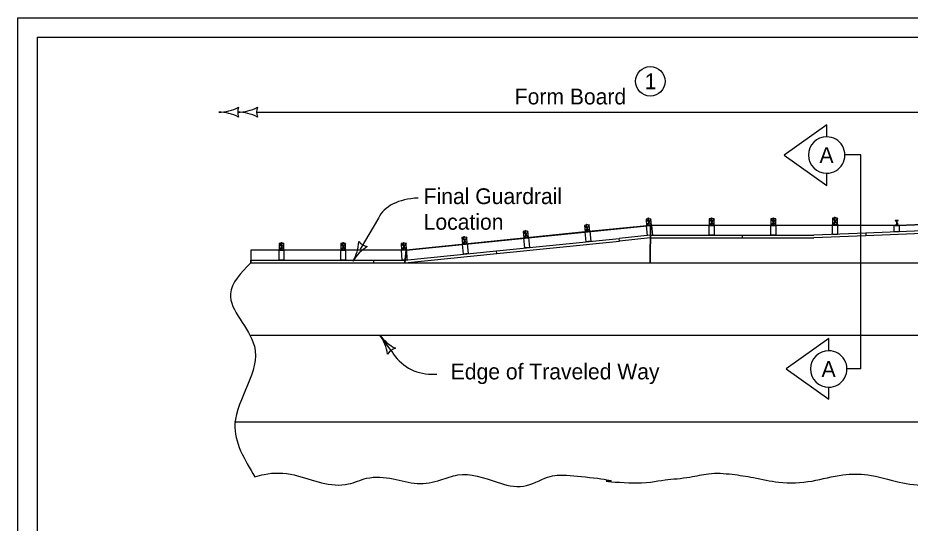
# Model space of a CAD drawing. Extents: x 10133 to 81668, y 7924 to 12229.
# Drawn here: x 10133 to 11037, y 9431 to 9944 of the extents above; entities that cross this region are included whole.
import ezdxf

# ---------------------------------------------------------------- set-up
doc = ezdxf.new("R2010")
doc.units = 0
for name, color, linetype in [('Cell', 7, 'Continuous'), ('dsnTextFinalPlan', 7, 'Continuous'), ('Level 1', 7, 'Continuous'), ('Level 12', 7, 'Continuous'), ('Level 4', 7, 'Continuous'), ('Level 5', 7, 'Continuous'), ('Level 6', 7, 'Continuous'), ('Level 7', 7, 'Continuous'), ('SheetBorder', 7, 'Continuous')]:
    doc.layers.add(name, color=color, linetype=linetype)

msp = doc.modelspace()

# ---------------------------------------------------------------- linework, layer by layer
at = {"layer": 'Cell'}
for p, q in [((11025.35, 9738.32), (11022.02, 9738.32)), ((11022.02, 9738.32), (11022.02, 9738.16)), ((11022.02, 9738.32), (11022.02, 9738.16)), ((11025.35, 9738.32), (11022.02, 9738.32)), ((11022.02, 9738.16), (11023.19, 9738.16)), ((11022.02, 9738.16), (11023.19, 9738.16)), ((11023.61, 9737.75), (11023.61, 9734)), ((11023.61, 9737.75), (11023.61, 9734)), ((11023.77, 9734), (11023.77, 9737.75)), ((11023.77, 9734), (11023.77, 9737.75)), ((11024.18, 9738.16), (11025.35, 9738.16)), ((11024.18, 9738.16), (11025.35, 9738.16)), ((11025.35, 9738.16), (11025.35, 9738.32)), ((11025.35, 9738.16), (11025.35, 9738.32)), ((11021.08, 9726.77), (11021.08, 9733.74)), ((11021.08, 9733.74), (11021.71, 9733.74)), ((11021.71, 9733.42), (11021.71, 9733.74)), ((11025.46, 9733.42), (11021.71, 9733.42)), ((11023.19, 9733.58), (11022.02, 9733.58)), ((11022.02, 9733.58), (11022.02, 9733.42)), ((11022.02, 9733.58), (11022.02, 9733.42)), ((11023.19, 9733.58), (11022.02, 9733.58)), ((11022.02, 9733.42), (11025.35, 9733.42)), ((11022.02, 9733.42), (11025.35, 9733.42)), ((11024, 9734.1), (11023.92, 9734.05)), ((11024, 9734.1), (11023.92, 9734.05)), ((11023.92, 9734.05), (11023.92, 9733.67)), ((11023.92, 9733.67), (11023.92, 9734.05)), ((11024, 9734.1), (11024.97, 9734.1)), ((11024.97, 9734.1), (11024, 9734.1)), ((11025.35, 9733.58), (11024.18, 9733.58)), ((11025.35, 9733.58), (11024.18, 9733.58)), ((11024.22, 9734.05), (11024.22, 9733.63)), ((11024.22, 9733.63), (11024.22, 9734.05)), ((11024.22, 9733.63), (11024.22, 9734.05)), ((11024.78, 9735.61), (11024.26, 9735.61)), ((11024.26, 9735.61), (11024.26, 9734.1)), ((11024.78, 9735.61), (11024.26, 9735.61)), ((11024.26, 9735.61), (11024.26, 9734.1)), ((11024.26, 9734.1), (11024.78, 9734.1)), ((11024.78, 9734.1), (11024.78, 9735.61)), ((11024.78, 9734.1), (11024.78, 9735.61)), ((11024.82, 9733.63), (11024.82, 9734.05)), ((11024.82, 9734.05), (11024.82, 9733.63)), ((11024.82, 9733.63), (11024.82, 9734.05)), ((11024.97, 9734.1), (11025.04, 9734.1)), ((11025.04, 9734.1), (11024.97, 9734.1)), ((11025.12, 9734.05), (11025.04, 9734.1)), ((11025.12, 9734.05), (11025.04, 9734.1)), ((11025.04, 9733.58), (11025.12, 9733.63)), ((11025.04, 9733.58), (11025.12, 9733.63)), ((11025.12, 9733.63), (11025.12, 9734.05)), ((11025.12, 9733.63), (11025.12, 9734.05)), ((11025.35, 9733.42), (11025.35, 9733.58)), ((11025.35, 9733.42), (11025.35, 9733.58)), ((11025.46, 9733.74), (11026.08, 9733.74)), ((11025.46, 9733.74), (11025.46, 9733.42)), ((11026.08, 9733.74), (11026.08, 9726.77)), ((11026.08, 9726.77), (11021.08, 9726.77))]:
    msp.add_line(p, q, dxfattribs=at)
for points in [[(11023.92, 9733.67), (11023.92, 9733.67)], [(11024.18, 9733.58), (11025.04, 9733.58), (11025.04, 9733.58)]]:
    msp.add_lwpolyline(points, dxfattribs=at)
for centre, start, end in [((11023.19, 9737.75), 359.99336, 90.00253), ((11023.19, 9737.75), 359.99336, 90.00253), ((11024.18, 9737.75), 90.00734, 179.99635), ((11024.18, 9737.75), 90.00734, 179.99635), ((11023.19, 9734), 270.00734, 359.99635), ((11023.19, 9734), 270.00734, 359.99635), ((11024.18, 9734), 179.99336, 270.00253), ((11024.18, 9734), 179.99336, 270.00253), ((11024.18, 9734), 230.88662, 270.00253)]:
    msp.add_arc(centre, 0.417, start, end, dxfattribs=at)
for points in [[(11024.22, 9734.05), (11024.2, 9734.06), (11024.15, 9734.09), (11024.06, 9734.1), (11023.99, 9734.09), (11023.94, 9734.06), (11023.92, 9734.05)], [(11024.22, 9734.05), (11024.2, 9734.06), (11024.15, 9734.09), (11024.06, 9734.1), (11023.99, 9734.09), (11023.94, 9734.06), (11023.92, 9734.05)], [(11023.92, 9734.05), (11023.94, 9734.06), (11023.99, 9734.09), (11024.06, 9734.1), (11024.15, 9734.09), (11024.2, 9734.06), (11024.22, 9734.05)], [(11024.12, 9733.59), (11024.13, 9733.59), (11024.17, 9733.6), (11024.2, 9733.62), (11024.22, 9733.63)], [(11024.82, 9734.05), (11024.77, 9734.06), (11024.66, 9734.09), (11024.51, 9734.1), (11024.36, 9734.09), (11024.27, 9734.06), (11024.22, 9734.05)], [(11024.82, 9734.05), (11024.77, 9734.06), (11024.66, 9734.09), (11024.51, 9734.1), (11024.36, 9734.09), (11024.27, 9734.06), (11024.22, 9734.05)], [(11024.22, 9734.05), (11024.27, 9734.06), (11024.36, 9734.09), (11024.51, 9734.1), (11024.66, 9734.09), (11024.77, 9734.06), (11024.82, 9734.05)], [(11024.22, 9733.63), (11024.27, 9733.62), (11024.38, 9733.59), (11024.54, 9733.58), (11024.69, 9733.59), (11024.78, 9733.62), (11024.82, 9733.63)], [(11024.82, 9733.63), (11024.78, 9733.62), (11024.69, 9733.59), (11024.54, 9733.58), (11024.38, 9733.59), (11024.27, 9733.62), (11024.22, 9733.63)], [(11024.22, 9733.63), (11024.27, 9733.62), (11024.38, 9733.59), (11024.54, 9733.58), (11024.69, 9733.59), (11024.78, 9733.62), (11024.82, 9733.63)], [(11025.12, 9734.05), (11025.11, 9734.06), (11025.07, 9734.08), (11025.01, 9734.1), (11024.94, 9734.1), (11024.87, 9734.08), (11024.83, 9734.06), (11024.82, 9734.05)], [(11025.12, 9734.05), (11025.11, 9734.06), (11025.07, 9734.08), (11025.01, 9734.1), (11024.94, 9734.1), (11024.87, 9734.08), (11024.83, 9734.06), (11024.82, 9734.05)], [(11024.82, 9734.05), (11024.83, 9734.06), (11024.87, 9734.08), (11024.94, 9734.1), (11025.01, 9734.1), (11025.07, 9734.08), (11025.11, 9734.06), (11025.12, 9734.05)], [(11024.82, 9733.63), (11024.83, 9733.63), (11024.87, 9733.6), (11024.94, 9733.58), (11025.01, 9733.58), (11025.07, 9733.6), (11025.11, 9733.62), (11025.12, 9733.63)], [(11025.12, 9733.63), (11025.11, 9733.62), (11025.07, 9733.6), (11025.01, 9733.58), (11024.94, 9733.58), (11024.87, 9733.6), (11024.83, 9733.63), (11024.82, 9733.63)], [(11024.82, 9733.63), (11024.83, 9733.63), (11024.87, 9733.6), (11024.94, 9733.58), (11025.01, 9733.58), (11025.07, 9733.6), (11025.11, 9733.62), (11025.12, 9733.63)]]:
    msp.add_open_spline(points, degree=3, dxfattribs=at)
at = {"layer": 'dsnTextFinalPlan'}
for p, q in [((11025.35, 9733.42), (11500.75, 9752.95)), ((11403.96, 9741.99), (10992.39, 9725.53)), ((11404.06, 9739.28), (10992.39, 9722.82)), ((11022.02, 9738.32), (11022.02, 9738.16)), ((11025.35, 9738.32), (11022.02, 9738.32)), ((11022.02, 9738.16), (11023.19, 9738.16)), ((11023.61, 9737.75), (11023.61, 9734)), ((11023.77, 9734), (11023.77, 9737.75)), ((11024.18, 9738.16), (11025.35, 9738.16)), ((11025.35, 9738.16), (11025.35, 9738.32)), ((10526.39, 9708.35), (10774.18, 9733.42)), ((11022.02, 9733.42), (10774.18, 9733.42)), ((11021.08, 9726.77), (11021.08, 9733.74)), ((11021.08, 9733.74), (11021.71, 9733.74)), ((11021.71, 9733.42), (11021.71, 9733.74)), ((11025.46, 9733.42), (11021.71, 9733.42)), ((11022.02, 9733.58), (11022.02, 9733.42)), ((11023.19, 9733.58), (11022.02, 9733.58)), ((11022.02, 9733.42), (11025.35, 9733.42)), ((11024, 9734.1), (11023.92, 9734.05)), ((11023.92, 9733.67), (11023.92, 9734.05)), ((11024, 9734.1), (11024.97, 9734.1)), ((11025.35, 9733.58), (11024.18, 9733.58)), ((11024.22, 9733.63), (11024.22, 9734.05)), ((11024.78, 9735.61), (11024.26, 9735.61)), ((11024.26, 9735.61), (11024.26, 9734.1)), ((11024.78, 9734.1), (11024.78, 9735.61)), ((11024.82, 9733.63), (11024.82, 9734.05)), ((11024.97, 9734.1), (11025.04, 9734.1)), ((11025.12, 9734.05), (11025.04, 9734.1)), ((11025.04, 9733.58), (11025.12, 9733.63)), ((11025.12, 9733.63), (11025.12, 9734.05)), ((11025.35, 9733.42), (11025.35, 9733.58)), ((11025.46, 9733.74), (11026.08, 9733.74)), ((11025.46, 9733.74), (11025.46, 9733.42)), ((11026.08, 9733.74), (11026.08, 9726.77)), ((10992.39, 9725.53), (10939.63, 9723.42)), ((10992.5, 9722.82), (10939.65, 9720.71)), ((10992.39, 9725.53), (10992.5, 9722.82)), ((10992.39, 9725.53), (10992.5, 9722.82)), ((11026.08, 9726.77), (11021.08, 9726.77)), ((10368.67, 9708.35), (10368.64, 9698.34)), ((10526.39, 9708.35), (10368.67, 9708.35)), ((10368.64, 9695.63), (11982.35, 9695.63)), ((10368.86, 9622), (11982.65, 9622))]:
    msp.add_line(p, q, dxfattribs=at)
for centre, start, end in [((11023.19, 9737.75), 359.99336, 90.00253), ((11024.18, 9737.75), 90.00734, 179.99635), ((11023.19, 9734), 270.00734, 359.99635), ((11024.18, 9734), 264.71743, 270.00253)]:
    msp.add_arc(centre, 0.417, start, end, dxfattribs=at)
for points in [[(11024.22, 9734.05), (11024.2, 9734.06), (11024.15, 9734.09), (11024.06, 9734.1), (11023.99, 9734.09), (11023.94, 9734.06), (11023.92, 9734.05)], [(11024.12, 9733.59), (11024.13, 9733.59), (11024.17, 9733.6), (11024.2, 9733.62), (11024.22, 9733.63)], [(11024.82, 9734.05), (11024.77, 9734.06), (11024.66, 9734.09), (11024.51, 9734.1), (11024.36, 9734.09), (11024.27, 9734.06), (11024.22, 9734.05)], [(11024.22, 9733.63), (11024.27, 9733.62), (11024.38, 9733.59), (11024.54, 9733.58), (11024.69, 9733.59), (11024.78, 9733.62), (11024.82, 9733.63)], [(11025.12, 9734.05), (11025.11, 9734.06), (11025.07, 9734.08), (11025.01, 9734.1), (11024.94, 9734.1), (11024.87, 9734.08), (11024.83, 9734.06), (11024.82, 9734.05)], [(11024.82, 9733.63), (11024.83, 9733.63), (11024.87, 9733.6), (11024.94, 9733.58), (11025.01, 9733.58), (11025.07, 9733.6), (11025.11, 9733.62), (11025.12, 9733.63)]]:
    msp.add_open_spline(points, degree=3, dxfattribs=at)
for points in [[(10368.64, 9695.63), (10347.99, 9664.08), (10372.36, 9611), (10352.66, 9531.9), (10372.93, 9478.29)], [(10372.93, 9478.29), (10382.36, 9480.86), (10412.58, 9480.29), (10440.52, 9472.31), (10467.89, 9471.16), (10486.14, 9476.87), (10512.94, 9476.3), (10537.46, 9471.74), (10561.41, 9475.16), (10578.52, 9480.29), (10618.43, 9472.88), (10645.23, 9468.88), (10669.75, 9478.01), (10692.56, 9479.72), (10731.34, 9474.02), (10730.77, 9474.02), (10751.92, 9472.41), (10788.99, 9475.27), (10814.08, 9478.12), (10832.9, 9481.54), (10856.85, 9480.97), (10878.51, 9477.55), (10904.17, 9472.98), (10937.82, 9474.13), (10969.18, 9480.4), (10994.27, 9480.4), (11026.2, 9472.98), (11055.29, 9470.13), (11088.93, 9476.98), (11121.43, 9480.4), (11155.65, 9473.55), (11181.31, 9470.7), (11203.54, 9474.13), (11231.49, 9489.53), (11241.75, 9491.81), (11266.27, 9494.09), (11296.93, 9494.66), (11318.03, 9494.66), (11371.34, 9485.38)]]:
    msp.add_spline(points, degree=3, dxfattribs=at)
at = {"layer": 'Level 1'}
for q in [(10152.18, 8314.36), (13247.87, 9924.36)]:
    msp.add_line((10152.18, 9924.36), q, dxfattribs=at)
at = {"layer": 'Level 12'}
msp.add_circle((10773.85, 9879.62), 15, dxfattribs=at)
at = {"layer": 'Level 4'}
for p, q in [((10769.49, 9739.76), (10775.13, 9733.62)), ((10774.47, 9740.26), (10770.15, 9733.13)), ((10771.88, 9740.98), (10771.87, 9741.04)), ((10772.64, 9733.37), (10771.98, 9740.01)), ((10833.64, 9740.09), (10838.64, 9733.42)), ((10838.64, 9740.09), (10833.64, 9733.42)), ((10836.14, 9741.06), (10836.14, 9741.13)), ((10836.14, 9733.42), (10836.14, 9740.09)), ((10896.14, 9740.09), (10901.14, 9733.42)), ((10901.14, 9740.09), (10896.14, 9733.42)), ((10898.64, 9741.06), (10898.64, 9741.13)), ((10898.64, 9733.42), (10898.64, 9740.09)), ((10958.64, 9740.95), (10963.64, 9734.28)), ((10963.64, 9740.95), (10958.64, 9734.28)), ((10961.14, 9741.92), (10961.14, 9741.99)), ((10961.14, 9734.28), (10961.14, 9740.95)), ((10644.84, 9727.23), (10650.48, 9721.1)), ((10649.81, 9727.73), (10645.51, 9720.6)), ((10647.23, 9728.45), (10647.22, 9728.52)), ((10647.99, 9720.85), (10647.33, 9727.48)), ((10707.03, 9733.48), (10712.67, 9727.35)), ((10712, 9733.98), (10707.69, 9726.85)), ((10707.69, 9726.85), (10712.67, 9727.35)), ((10709.42, 9734.7), (10709.41, 9734.77)), ((10710.18, 9727.1), (10709.51, 9733.73)), ((10712.67, 9727.35), (10713.67, 9717.39)), ((10770.15, 9733.13), (10775.13, 9733.62)), ((10772.64, 9733.37), (10770.15, 9733.13)), ((10772.64, 9733.37), (10770.15, 9733.13)), ((10771.15, 9723.17), (10770.15, 9733.13)), ((10775.13, 9733.62), (10776.13, 9723.66)), ((10833.64, 9733.42), (10838.64, 9733.42)), ((10833.64, 9723.42), (10833.64, 9733.42)), ((10838.64, 9733.42), (10838.64, 9723.42)), ((10896.14, 9733.42), (10901.14, 9733.42)), ((10896.14, 9723.42), (10896.14, 9733.42)), ((10901.14, 9733.42), (10901.14, 9723.42)), ((10958.64, 9734.28), (10963.64, 9734.28)), ((10958.64, 9724.28), (10958.64, 9734.28)), ((10963.64, 9734.28), (10963.64, 9724.28)), ((10582.66, 9721.02), (10588.3, 9714.85)), ((10587.64, 9721.52), (10583.33, 9714.35)), ((10585.05, 9722.24), (10585.05, 9722.31)), ((10585.81, 9714.6), (10585.15, 9721.27)), ((10617.9, 9707.76), (10742.28, 9720.26)), ((10645.51, 9720.6), (10650.49, 9721.1)), ((10646.51, 9710.64), (10645.51, 9720.6)), ((10650.49, 9721.1), (10651.49, 9711.14)), ((10708.69, 9716.89), (10707.69, 9726.85)), ((10773.64, 9723.42), (10742.28, 9720.26)), ((10742.55, 9717.57), (10742.28, 9720.26)), ((10742.55, 9717.58), (10742.28, 9720.26)), ((10773.64, 9720.71), (10742.55, 9717.58)), ((10776.13, 9723.66), (10771.15, 9723.17)), ((10773.64, 9723.42), (10867.39, 9723.42)), ((10773.64, 9720.71), (10867.39, 9720.71)), ((10838.64, 9723.42), (10833.64, 9723.42)), ((10867.39, 9720.7), (10867.39, 9723.42)), ((10867.39, 9723.42), (10939.63, 9723.42)), ((10867.39, 9720.71), (10867.39, 9723.42)), ((10867.39, 9720.71), (10939.65, 9720.71)), ((10901.14, 9723.42), (10896.14, 9723.42)), ((10963.64, 9724.28), (10958.64, 9724.28)), ((10397.39, 9715.02), (10402.39, 9708.35)), ((10402.39, 9715.02), (10397.39, 9708.35)), ((10399.89, 9715.99), (10399.89, 9716.06)), ((10399.89, 9708.35), (10399.89, 9715.02)), ((10459.89, 9715.02), (10464.89, 9708.35)), ((10464.89, 9715.02), (10459.89, 9708.35)), ((10462.39, 9715.99), (10462.39, 9716.06)), ((10462.39, 9708.35), (10462.39, 9715.02)), ((10521.28, 9715.08), (10526.61, 9708.64)), ((10526.28, 9715.33), (10521.62, 9708.39)), ((10523.73, 9716.18), (10523.73, 9716.25)), ((10524.11, 9708.51), (10523.78, 9715.2)), ((10583.33, 9714.35), (10588.3, 9714.85)), ((10584.32, 9704.34), (10583.33, 9714.35)), ((10588.3, 9714.85), (10589.3, 9704.84)), ((10618.17, 9705.07), (10742.55, 9717.57)), ((10651.49, 9711.14), (10646.51, 9710.64)), ((10713.67, 9717.39), (10708.69, 9716.89)), ((10397.39, 9708.35), (10402.4, 9708.35)), ((10397.39, 9698.34), (10397.39, 9708.35)), ((10402.4, 9708.35), (10402.4, 9698.34)), ((10459.89, 9708.35), (10464.9, 9708.35)), ((10459.89, 9698.34), (10459.89, 9708.35)), ((10464.9, 9708.35), (10464.9, 9698.34)), ((10521.62, 9708.39), (10526.61, 9708.64)), ((10522.11, 9698.34), (10521.62, 9708.39)), ((10524.62, 9698.34), (10617.9, 9707.76)), ((10524.89, 9695.63), (10618.17, 9705.06)), ((10526.61, 9708.64), (10527.11, 9698.59)), ((10589.3, 9704.84), (10584.32, 9704.34)), ((10618.17, 9705.06), (10617.9, 9707.76)), ((10618.17, 9705.07), (10617.9, 9707.76)), ((10368.64, 9698.34), (10493.64, 9698.34)), ((10368.64, 9695.63), (10368.64, 9698.34)), ((10368.64, 9695.63), (10493.64, 9695.63)), ((10402.4, 9698.34), (10397.39, 9698.34)), ((10464.9, 9698.34), (10459.89, 9698.34)), ((10493.64, 9698.34), (10524.62, 9698.34)), ((10493.64, 9695.63), (10493.64, 9698.34)), ((10493.64, 9695.63), (10524.89, 9695.63)), ((10527.11, 9698.59), (10522.11, 9698.34)), ((10352.26, 9534.09), (11994.29, 9534.09))]:
    msp.add_line(p, q, dxfattribs=at)
for points in [[(10770.15, 9733.13), (10775.13, 9733.62), (10774.47, 9740.26), (10769.49, 9739.76)], [(10833.64, 9733.42), (10838.64, 9733.42), (10838.64, 9740.09), (10833.64, 9740.09)], [(10896.14, 9733.42), (10901.14, 9733.42), (10901.14, 9740.09), (10896.14, 9740.09)], [(10958.64, 9734.28), (10963.64, 9734.28), (10963.64, 9740.95), (10958.64, 9740.95)], [(10645.51, 9720.6), (10650.48, 9721.1), (10649.81, 9727.73), (10644.84, 9727.23)], [(10707.69, 9726.85), (10712.67, 9727.35), (10712, 9733.98), (10707.03, 9733.48)], [(10583.33, 9714.35), (10588.3, 9714.85), (10587.64, 9721.52), (10582.66, 9721.02)], [(10397.39, 9708.35), (10402.39, 9708.35), (10402.39, 9715.02), (10397.39, 9715.02)], [(10459.89, 9708.35), (10464.89, 9708.35), (10464.89, 9715.02), (10459.89, 9715.02)], [(10521.62, 9708.39), (10526.61, 9708.64), (10526.28, 9715.33), (10521.28, 9715.08)]]:
    msp.add_lwpolyline(points, close=True, dxfattribs=at)
for points in [[(10771.65, 9739.97), (10771.6, 9740.4), (10772.27, 9740.47), (10772.31, 9740.04)], [(10771.74, 9740.42), (10771.69, 9740.96), (10772.08, 9740.99), (10772.13, 9740.46)], [(10835.8, 9740.09), (10835.8, 9740.52), (10836.47, 9740.52), (10836.47, 9740.09)], [(10835.94, 9740.52), (10835.94, 9741.06), (10836.33, 9741.06), (10836.33, 9740.52)], [(10898.31, 9740.09), (10898.31, 9740.52), (10898.97, 9740.52), (10898.97, 9740.09)], [(10898.45, 9740.52), (10898.45, 9741.06), (10898.83, 9741.06), (10898.83, 9740.52)], [(10960.81, 9740.95), (10960.81, 9741.38), (10961.47, 9741.38), (10961.47, 9740.95)], [(10960.95, 9741.38), (10960.95, 9741.92), (10961.33, 9741.92), (10961.33, 9741.38)], [(10647, 9727.45), (10646.95, 9727.87), (10647.62, 9727.94), (10647.66, 9727.51)], [(10647.09, 9727.89), (10647.04, 9728.43), (10647.42, 9728.47), (10647.48, 9727.93)], [(10709.18, 9733.7), (10709.14, 9734.12), (10709.8, 9734.19), (10709.85, 9733.76)], [(10709.28, 9734.14), (10709.22, 9734.68), (10709.61, 9734.72), (10709.66, 9734.18)], [(10584.82, 9721.23), (10584.78, 9721.66), (10585.44, 9721.73), (10585.48, 9721.3)], [(10584.91, 9721.68), (10584.86, 9722.22), (10585.25, 9722.26), (10585.3, 9721.72)], [(10399.56, 9715.02), (10399.56, 9715.45), (10400.23, 9715.45), (10400.23, 9715.02)], [(10399.7, 9715.45), (10399.7, 9715.99), (10400.09, 9715.99), (10400.09, 9715.45)], [(10462.06, 9715.02), (10462.06, 9715.45), (10462.73, 9715.45), (10462.73, 9715.02)], [(10462.2, 9715.45), (10462.2, 9715.99), (10462.59, 9715.99), (10462.59, 9715.45)], [(10523.45, 9715.19), (10523.43, 9715.62), (10524.09, 9715.65), (10524.11, 9715.22)], [(10523.57, 9715.63), (10523.54, 9716.17), (10523.93, 9716.19), (10523.95, 9715.65)], [(10524.11, 9708.51), (10521.62, 9708.39), (10521.62, 9708.39)]]:
    msp.add_lwpolyline(points, dxfattribs=at)
at = {"layer": 'Level 5'}
for p, q in [((10375.45, 9848.49), (11397.86, 9848.49)), ((11500.75, 9752.95), (11025.46, 9733.42)), ((10774.18, 9733.42), (10707.69, 9726.85)), ((10774.18, 9733.42), (10773.8, 9695.63)), ((10773.8, 9695.63), (10774.18, 9733.42)), ((11025.46, 9733.42), (10774.18, 9733.42)), ((10774.18, 9733.42), (10774.18, 9733.42)), ((10707.69, 9726.83), (10526.39, 9708.35)), ((10707.69, 9726.85), (10707.69, 9726.83)), ((10368.67, 9708.35), (10368.64, 9695.63)), ((10526.39, 9708.34), (10368.67, 9708.35)), ((10526.39, 9708.34), (10524.89, 9695.63)), ((10524.89, 9695.63), (10526.39, 9708.34)), ((10526.39, 9708.35), (10526.39, 9708.34)), ((10526.39, 9708.34), (10526.39, 9708.34)), ((10368.64, 9695.63), (10524.89, 9695.63)), ((10524.89, 9695.63), (10773.8, 9695.63)), ((10773.8, 9695.63), (11805.49, 9695.63))]:
    msp.add_line(p, q, dxfattribs=at)
for centre, radius, start, end in [((10336.23, 9890.84), 42.5, 270, 298.07249), ((10336.23, 9805.84), 42.5, 61.92751, 90), ((10355.45, 9890.84), 42.5, 270, 298.07249), ((10371.87, 9848.34), 16.42, 162.26665, 197.73335), ((10355.45, 9805.84), 42.5, 61.92751, 90), ((10391.09, 9848.34), 16.42, 162.26665, 197.73335)]:
    msp.add_arc(centre, radius, start, end, dxfattribs=at)
at = {"layer": 'Level 6'}
for p, q in [((10498.16, 9740.72), (10479.61, 9709.38)), ((10511.77, 9605.55), (10499.66, 9622)), ((10551.86, 9582.48), (10557.31, 9582.48))]:
    msp.add_line(p, q, dxfattribs=at)
for centre, radius, start, end in [((10435.84, 9718.88), 42.5, 329.37973, 357.45222), ((10508.99, 9675.59), 42.5, 121.30724, 149.37973), ((10490.57, 9727.9), 16.42, 221.64638, 257.11308), ((10533.88, 9647.21), 42.5, 216.37256, 244.44505), ((10465.44, 9596.8), 42.5, 8.30007, 36.37256), ((10520.79, 9593.31), 16.42, 108.63921, 144.10591), ((10551.92, 9628.94), 46.46, 210.22743, 270)]:
    msp.add_arc(centre, radius, start, end, dxfattribs=at)
msp.add_ellipse((10579.25, 9701.68), major_axis=(-81.09, 39.04), ratio=0.555556, start_param=5.482641, end_param=6.283185, dxfattribs=at)
at = {"layer": 'Level 7'}
for p, q in [((10987.26, 9805.1), (10971.49, 9805.1)), ((10987.26, 9587.81), (10987.26, 9805.1)), ((10987.26, 9587.81), (10973.31, 9587.81))]:
    msp.add_line(p, q, dxfattribs=at)
for points in [[(10952.7, 9823.28), (10952.7, 9835.61), (10909.57, 9804.8), (10952.7, 9773.99), (10952.7, 9786.31)], [(10954.82, 9606.3), (10954.82, 9618.62), (10911.69, 9587.81), (10954.82, 9557), (10954.82, 9569.33)]]:
    msp.add_lwpolyline(points, dxfattribs=at)
for centre, start, end in [((10952.7, 9804.8), 90.00083, 269.99917), ((10952.7, 9804.8), 269.99917, 90.00083), ((10954.82, 9587.81), 90.00083, 269.99917), ((10954.82, 9587.81), 269.99917, 90.00083)]:
    msp.add_arc(centre, 18.49, start, end, dxfattribs=at)
at = {"layer": 'SheetBorder'}
msp.add_lwpolyline([(10132.52, 9944.02), (13267.53, 9944.02), (13267.53, 7924.02), (10132.52, 7924.02)], close=True, dxfattribs=at)

# ---------------------------------------------------------------- texts
at = {"layer": 'Level 12'}
msp.add_text('1', height=16, dxfattribs=at).set_placement((10768.23, 9871.62))
at = {"layer": 'Level 5'}
msp.add_text('Form Board', height=16, dxfattribs=at).set_placement((10636.4, 9856.18))
at = {"layer": 'Level 6'}
for s, p in [('Final Guardrail ', (10544.06, 9755.05)), ('Location', (10544.06, 9729.05)), ('Edge of Traveled Way', (10571.5, 9577.21))]:
    msp.add_text(s, height=16, dxfattribs=at).set_placement(p)
at = {"layer": 'Level 7'}
for p in [(10945.42, 9796.8), (10947.52, 9579.81)]:
    msp.add_text('A', height=16, dxfattribs=at).set_placement(p)

doc.saveas('drawing.dxf')
